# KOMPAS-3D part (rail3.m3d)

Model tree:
1. X Axis
2. Y Axis
3. Z Axis
4. Origin
     Wall Thickness 1 = 1; Wall Thickness 2 = 1; Distance 1 = 50; Distance 2 = 10

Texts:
  Steel DIN 17102
  Three Point Plane
  Plane at Angle
  Line and Point Plane
  Axis through Two Vertices
  Axis of Feature
  Axis of Conical Surface
  Axis through Edge
  Trim by Surface
  Trim by Sketch
  Feature with No History
  Intersection Axis of Two Planes
  Two Line Plane
  Line and Face Plane
  Bend by line
  Hole in sheet body
  Cut in sheet body
  Point in CM
  Linear Dimension from Line to Point
  Surface Finish Symbol
  Geometric Tolerance Symbol
  Leader #1
  Leader #2
  Leader #3
  Shape Deviations and Datum
  Node point number
  Mark of coordination axis
  Node point designation
  Mark/Reference designation with leader
  Mark/reference designation on line
  Mark/Reference designation without leader
  LR2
